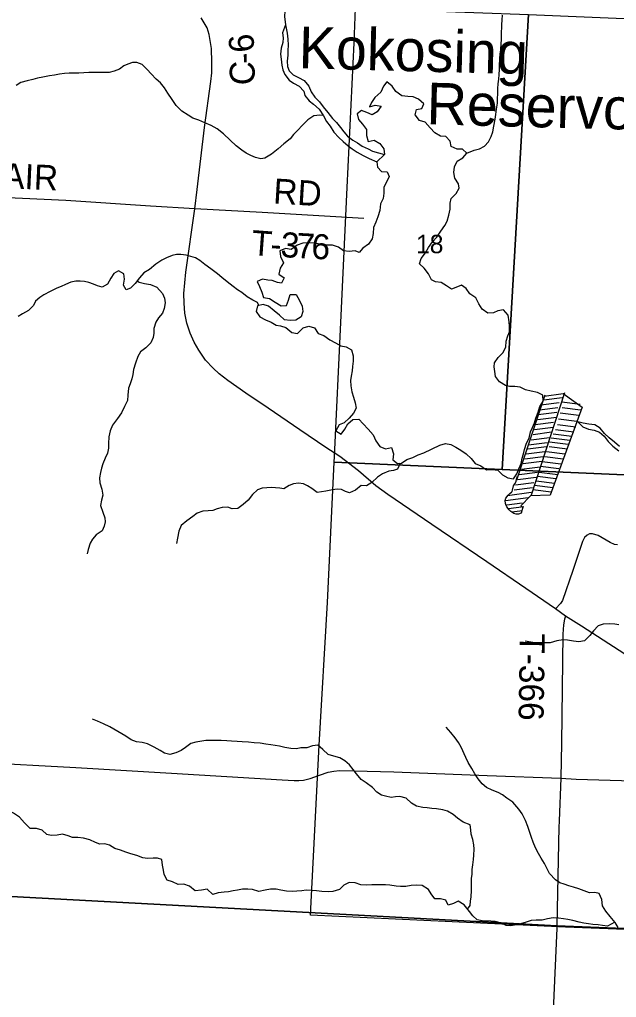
# Model space of a CAD drawing. Extents: x 1759416 to 2214760, y 252598 to 1116833.
# Drawn here: x 1940879 to 1948045, y 906081 to 917809 of the extents above; entities that cross this region are included whole.
import ezdxf

# ---------------------------------------------------------------- set-up
doc = ezdxf.new("R2010")
doc.units = 0
for name, color, linetype in [('GM_X_County_Road', 7, 'Continuous'), ('GM_X_County_Road_Text', 7, 'Continuous'), ('GM_X_Major_Lake', 7, 'Continuous'), ('GM_X_Major_Lake_Text', 7, 'Continuous'), ('GM_X_Major_River', 7, 'Continuous'), ('GM_X_Minor_Lake', 7, 'Continuous'), ('GM_X_Minor_River', 7, 'Continuous'), ('GM_X_Section', 7, 'Continuous'), ('GM_X_Section_Text', 7, 'Continuous'), ('GM_X_Township', 7, 'Continuous'), ('GM_X_Township_Road', 7, 'Continuous'), ('GM_X_Township_Road_Text', 7, 'Continuous')]:
    doc.layers.add(name, color=color, linetype=linetype)

msp = doc.modelspace()

# ---------------------------------------------------------------- linework, layer by layer
at = {"layer": 'GM_X_County_Road'}
for points in [[(1948338, 910072), (1947626, 910533), (1947434, 910655), (1947314, 910743), (1946955, 910986), (1946490, 911306), (1945827, 911752), (1945302, 912113), (1945158, 912217), (1944947, 912395), (1944725, 912567), (1944554, 912676), (1944244, 912890), (1943863, 913147), (1943594, 913328), (1943380, 913478), (1943274, 913560), (1943203, 913628), (1943113, 913722), (1943031, 913842), (1942974, 913940), (1942926, 914046), (1942888, 914168), (1942865, 914288), (1942855, 914406), (1942853, 914523), (1942876, 914779), (1942984, 915539), (1943011, 915772), (1943099, 916512), (1943174, 917067), (1943186, 917169), (1943187, 917298), (1943183, 917462), (1943156, 917630), (1943130, 917708), (1943058, 917828)], [(1940369, 908903), (1941554, 908838), (1942702, 908771), (1944033, 908690), (1944174, 908682), (1944232, 908682), (1944288, 908687), (1944368, 908708), (1944479, 908747), (1944583, 908783), (1944653, 908795), (1944719, 908802), (1944891, 908798), (1945374, 908788), (1946494, 908742), (1947376, 908712), (1947560, 908700), (1948378, 908674)]]:
    msp.add_lwpolyline(points, dxfattribs=at)
at = {"layer": 'GM_X_Major_Lake'}
for points in [[(1946954, 913368), (1946890, 913398), (1946826, 913408), (1946761, 913406), (1946711, 913418), (1946641, 913463), (1946593, 913527), (1946584, 913589), (1946578, 913643), (1946582, 913693), (1946624, 913756), (1946680, 913812), (1946715, 913880), (1946721, 913952), (1946739, 914014), (1946759, 914064), (1946761, 914132), (1946758, 914184), (1946744, 914263), (1946688, 914327), (1946622, 914317), (1946570, 914293), (1946501, 914289), (1946433, 914334), (1946392, 914400), (1946356, 914470), (1946286, 914518), (1946242, 914583), (1946184, 914623), (1946118, 914597), (1946065, 914575), (1946005, 914615), (1945941, 914656), (1945873, 914662), (1945823, 914686), (1945790, 914760), (1945738, 914826), (1945682, 914877), (1945700, 914943), (1945754, 915009), (1945790, 915075), (1945837, 915141), (1945887, 915199), (1945937, 915271), (1945983, 915337), (1946012, 915391), (1946034, 915462), (1946050, 915534), (1946050, 915606), (1946060, 915662), (1946121, 915722), (1946155, 915786), (1946147, 915840), (1946103, 915905), (1946091, 915973), (1946100, 916041), (1946134, 916111), (1946200, 916151), (1946250, 916205), (1946198, 916255), (1946132, 916255), (1946062, 916286), (1946048, 916350), (1945998, 916406), (1945934, 916412), (1945866, 916451), (1945808, 916511), (1945748, 916577), (1945680, 916597), (1945628, 916664), (1945643, 916730), (1945709, 916740), (1945731, 916798), (1945669, 916854), (1945605, 916882), (1945539, 916885), (1945469, 916893), (1945397, 916945), (1945353, 917011), (1945289, 917062), (1945247, 917010), (1945217, 916939), (1945146, 916875), (1945106, 916813), (1945082, 916761), (1945150, 916781), (1945222, 916771), (1945174, 916701), (1945112, 916667), (1945048, 916693), (1944984, 916717), (1944931, 916679), (1944949, 916611), (1944997, 916553), (1945043, 916491), (1945043, 916418), (1945063, 916346), (1945135, 916364), (1945203, 916322), (1945253, 916258), (1945259, 916191)], [(1945259, 916191), (1945170, 916103)], [(1945170, 916103), (1945178, 916037), (1945224, 915985), (1945292, 915981), (1945318, 915926), (1945253, 915794), (1945251, 915728), (1945245, 915664), (1945213, 915598), (1945205, 915520), (1945182, 915441), (1945158, 915377), (1945130, 915313), (1945126, 915243), (1945112, 915177), (1945067, 915115), (1945001, 915065), (1944957, 915013), (1944907, 915035), (1944837, 915025), (1944769, 915033), (1944709, 915080), (1944634, 915102), (1944570, 915104), (1944514, 915114), (1944462, 915120), (1944412, 915126), (1944344, 915131), (1944278, 915127), (1944212, 915103), (1944141, 915051), (1944071, 915063), (1944003, 915035), (1944011, 914967), (1944047, 914889), (1944007, 914827), (1943990, 914756), (1944054, 914710), (1944024, 914646), (1943974, 914656), (1943910, 914678), (1943858, 914685), (1943794, 914697), (1943732, 914669), (1943760, 914607), (1943789, 914538), (1943809, 914474), (1943881, 914464), (1943949, 914418), (1944021, 914375), (1944082, 914379), (1944106, 914443), (1944128, 914513), (1944198, 914513), (1944240, 914441), (1944272, 914373), (1944278, 914309), (1944261, 914244), (1944197, 914202), (1944129, 914199), (1944061, 914209), (1943999, 914263), (1943935, 914315), (1943869, 914370), (1943803, 914392), (1943735, 914376), (1943719, 914308), (1943763, 914242), (1943833, 914207), (1943899, 914181), (1943961, 914143), (1944011, 914135), (1944077, 914117), (1944149, 914054), (1944217, 914044), (1944283, 914110), (1944351, 914132), (1944421, 914110), (1944465, 914043), (1944533, 914021), (1944603, 913967), (1944671, 913931), (1944735, 913896), (1944799, 913882), (1944863, 913848), (1944883, 913776), (1944885, 913712), (1944875, 913647), (1944871, 913595), (1944861, 913531), (1944854, 913479), (1944856, 913415), (1944868, 913343), (1944888, 913278), (1944910, 913212), (1944920, 913148), (1944887, 913086), (1944837, 913026), (1944777, 912972), (1944715, 912948), (1944674, 912876)], [(1945926, 912704), (1945992, 912726), (1946056, 912714), (1946116, 912680), (1946178, 912644), (1946242, 912599), (1946300, 912545), (1946350, 912485), (1946418, 912455), (1946486, 912410), (1946554, 912414), (1946620, 912406), (1946678, 912348), (1946740, 912311), (1946808, 912301), (1946847, 912359), (1946873, 912419), (1946899, 912483), (1946911, 912550), (1946927, 912602), (1946942, 912654), (1946966, 912728), (1946998, 912790), (1947014, 912864), (1947037, 912918), (1947059, 912970), (1947077, 913026), (1947103, 913101), (1947125, 913167), (1947164, 913233), (1947162, 913305), (1947096, 913335), (1947022, 913350), (1946954, 913368)], [(1944674, 912876), (1944738, 912836), (1944785, 912898), (1944819, 912962), (1944879, 913012), (1944951, 913017), (1945005, 912959), (1945065, 912895), (1945123, 912827), (1945157, 912758), (1945205, 912688), (1945273, 912660), (1945345, 912676), (1945369, 912601), (1945361, 912529), (1945415, 912483), (1945465, 912489), (1945527, 912533), (1945599, 912557), (1945665, 912587), (1945733, 912611), (1945926, 912704)]]:
    msp.add_lwpolyline(points, dxfattribs=at)
at = {"layer": 'GM_X_Major_River'}
for points in [[(1945259, 916191), (1945170, 916103)], [(1947580, 912983), (1947642, 912923), (1947708, 912897), (1947776, 912884), (1947842, 912862), (1947898, 912812), (1947944, 912750), (1948000, 912693), (1948072, 912637)], [(1948080, 912689), (1948020, 912742), (1947956, 912792), (1947902, 912846), (1947848, 912910), (1947784, 912947), (1947712, 912957), (1947646, 912969), (1947580, 912983)]]:
    msp.add_lwpolyline(points, dxfattribs=at)
at = {"layer": 'GM_X_Minor_Lake'}
for points in [[(1945259, 916191), (1945170, 916103)], [(1947175, 913293), (1947404, 913325), (1947635, 913158), (1947249, 912104), (1947012, 912098), (1946895, 911976), (1946921, 911960), (1946902, 911890), (1946868, 911878), (1946840, 911876), (1946812, 911883), (1946778, 911907), (1946758, 911927), (1946730, 911964), (1946718, 911992), (1946714, 912006), (1946707, 912042), (1946717, 912070), (1946745, 912106), (1946767, 912130), (1946784, 912142), (1946794, 912148), (1946798, 912164), (1946810, 912216), (1946823, 912240), (1946839, 912268), (1946843, 912296), (1946856, 912334)], [(1947185, 913304), (1946845, 912286)], [(1947422, 913331), (1947022, 912104), (1947013, 912097)], [(1947393, 913273), (1947172, 913244)], [(1947341, 913153), (1947120, 913125)], [(1947358, 913213), (1947137, 913185)], [(1947387, 913223), (1947608, 913195)], [(1947393, 913156), (1947614, 913127)], [(1947323, 913034), (1947102, 913006)], [(1947327, 913094), (1947106, 913066)], [(1947348, 913021), (1947569, 912992)], [(1947370, 913091), (1947591, 913063)], [(1947283, 912918), (1947062, 912890)], [(1947288, 912975), (1947067, 912947)], [(1947336, 912953), (1947557, 912925)], [(1947240, 912793), (1947019, 912765)], [(1947266, 912859), (1947045, 912830)], [(1947262, 912794), (1947483, 912766)], [(1947286, 912840), (1947507, 912812)], [(1947311, 912893), (1947532, 912865)], [(1947203, 912683), (1946982, 912655)], [(1947211, 912734), (1946990, 912705)], [(1947235, 912690), (1947456, 912662)], [(1947242, 912746), (1947463, 912718)], [(1947166, 912564), (1946945, 912536)], [(1947183, 912626), (1946962, 912598)], [(1947184, 912568), (1947405, 912540)], [(1947203, 912630), (1947424, 912602)], [(1947127, 912442), (1946906, 912413)], [(1947147, 912507), (1946925, 912479)], [(1947132, 912451), (1947353, 912423)], [(1947154, 912510), (1947375, 912482)], [(1947081, 912317), (1946860, 912288)], [(1947098, 912376), (1946877, 912348)], [(1947096, 912332), (1947317, 912303)], [(1947118, 912382), (1947339, 912354)], [(1947052, 912254), (1946831, 912226)], [(1947060, 912225), (1947281, 912196)], [(1947080, 912278), (1947301, 912250)], [(1947021, 912135), (1946735, 912098)], [(1947038, 912191), (1946817, 912163)], [(1947041, 912171), (1947262, 912143)], [(1946983, 912072), (1946714, 912038)], [(1946912, 912007), (1946729, 911983)], [(1946933, 911964), (1946750, 911941)], [(1946916, 911918), (1946789, 911902)]]:
    msp.add_lwpolyline(points, dxfattribs=at)
at = {"layer": 'GM_X_Minor_River'}
for points in [[(1943706, 918546), (1943784, 918468), (1943834, 918402), (1943874, 918344), (1943918, 918278), (1943956, 918223), (1944006, 918151), (1944036, 918099), (1944054, 918045), (1944066, 917965), (1944064, 917911), (1944058, 917844), (1944073, 917745)], [(1946250, 916205), (1946338, 916241), (1946402, 916259), (1946460, 916292), (1946510, 916344), (1946542, 916408), (1946559, 916462), (1946573, 916530), (1946589, 916612), (1946597, 916671), (1946605, 916735), (1946615, 916805), (1946615, 916861), (1946619, 916919), (1946621, 916981), (1946625, 917038), (1946631, 917094), (1946635, 917150), (1946639, 917208), (1946641, 917270), (1946645, 917326), (1946651, 917397), (1946657, 917453), (1946661, 917515), (1946663, 917575), (1946665, 917625), (1946669, 917746), (1946673, 917806), (1946675, 917860)], [(1944073, 917745), (1944034, 917650), (1944044, 917588), (1944038, 917533), (1944020, 917467), (1944013, 917395), (1944019, 917333), (1944029, 917261), (1944041, 917205), (1944063, 917150), (1944115, 917082), (1944166, 917044), (1944234, 917008), (1944290, 916948), (1944304, 916898), (1944356, 916835), (1944406, 916795), (1944474, 916733), (1944526, 916653), (1944564, 916585), (1944606, 916529), (1944650, 916460), (1944710, 916396), (1944766, 916346), (1944824, 916294), (1944874, 916260), (1944934, 916218), (1945006, 916178), (1945078, 916143), (1945170, 916103)], [(1944073, 917745), (1944090, 917644), (1944100, 917574), (1944102, 917501), (1944100, 917437), (1944098, 917381), (1944090, 917311), (1944094, 917245), (1944114, 917195), (1944162, 917144), (1944226, 917114), (1944294, 917076), (1944352, 917010), (1944378, 916942), (1944424, 916876), (1944478, 916823), (1944522, 916763), (1944578, 916693), (1944636, 916623), (1944684, 916573), (1944732, 916515), (1944774, 916462), (1944818, 916410), (1944882, 916362), (1944936, 916330), (1944992, 916292), (1945064, 916258), (1945118, 916232), (1945259, 916191)], [(1944523, 916657), (1944482, 916661), (1944410, 916655), (1944340, 916607), (1944271, 916539), (1944219, 916481), (1944169, 916430), (1944127, 916380), (1944053, 916318), (1943985, 916258), (1943905, 916196), (1943825, 916146), (1943774, 916140), (1943710, 916156), (1943654, 916180), (1943600, 916206), (1943546, 916242), (1943480, 916296), (1943406, 916364), (1943326, 916439), (1943252, 916497), (1943180, 916539), (1943104, 916571), (1943030, 916601), (1942960, 916627), (1942902, 916663), (1942829, 916711), (1942759, 916778), (1942711, 916848), (1942659, 916924), (1942621, 916988), (1942571, 917050), (1942521, 917093), (1942459, 917157), (1942411, 917209), (1942351, 917271), (1942289, 917295), (1942237, 917293), (1942181, 917273), (1942131, 917255), (1942081, 917215), (1942017, 917189), (1941956, 917175), (1941900, 917173), (1941822, 917173), (1941762, 917173), (1941710, 917173), (1941652, 917171), (1941590, 917167), (1941532, 917167), (1941474, 917165), (1941420, 917161), (1941360, 917153), (1941298, 917143), (1941237, 917135), (1941157, 917119), (1941095, 917105), (1941039, 917091), (1940969, 917075), (1940895, 917053), (1940839, 917019)], [(1943753, 914380), (1943735, 914415), (1943681, 914445), (1943611, 914483), (1943547, 914535), (1943495, 914567), (1943445, 914606), (1943373, 914662), (1943307, 914714), (1943255, 914758), (1943175, 914818), (1943105, 914872), (1943045, 914918), (1942993, 914949), (1942935, 914967), (1942881, 914981), (1942815, 914991), (1942764, 914989), (1942710, 914977), (1942642, 914951), (1942586, 914923), (1942514, 914876), (1942440, 914812), (1942370, 914770), (1942318, 914712), (1942268, 914644), (1942211, 914588), (1942161, 914568), (1942127, 914622), (1942139, 914694), (1942133, 914758), (1942069, 914796), (1942011, 914762), (1941977, 914708), (1941935, 914636), (1941869, 914598), (1941815, 914616), (1941765, 914634), (1941709, 914654), (1941659, 914668), (1941607, 914672), (1941555, 914670), (1941496, 914658), (1941430, 914630), (1941380, 914608), (1941328, 914588), (1941248, 914548), (1941172, 914506), (1941122, 914476), (1941072, 914432), (1941046, 914381), (1940986, 914319), (1940915, 914279), (1940861, 914249)], [(1942291, 914675), (1942316, 914658), (1942378, 914644), (1942450, 914630), (1942528, 914600), (1942594, 914525), (1942620, 914467), (1942628, 914411), (1942614, 914343), (1942594, 914287), (1942546, 914231), (1942514, 914179), (1942492, 914102), (1942490, 914046), (1942482, 913994), (1942455, 913930), (1942397, 913870), (1942331, 913822), (1942299, 913769), (1942271, 913689), (1942249, 913613), (1942241, 913551), (1942229, 913499), (1942209, 913441), (1942189, 913388), (1942181, 913302), (1942175, 913238), (1942139, 913166), (1942104, 913090), (1942056, 913023), (1941996, 912943), (1941968, 912875), (1941950, 912805), (1941946, 912723), (1941946, 912668), (1941936, 912608), (1941908, 912550), (1941880, 912482), (1941864, 912428), (1941850, 912376), (1941840, 912314), (1941842, 912251), (1941866, 912177), (1941878, 912103), (1941864, 912045), (1941852, 911979), (1941880, 911902), (1941904, 911834), (1941908, 911784), (1941897, 911734), (1941871, 911678), (1941799, 911630), (1941755, 911578), (1941725, 911527), (1941701, 911453), (1941691, 911399)], [(1945448, 912487), (1945417, 912415), (1945367, 912401), (1945311, 912391), (1945236, 912359), (1945178, 912319), (1945108, 912255), (1945044, 912217), (1944980, 912219), (1944914, 912166), (1944842, 912134), (1944792, 912148), (1944742, 912171), (1944690, 912177), (1944634, 912169), (1944557, 912153), (1944453, 912136), (1944387, 912183), (1944337, 912215), (1944287, 912239), (1944227, 912247), (1944169, 912239), (1944117, 912219), (1944053, 912179), (1944003, 912187), (1943953, 912193), (1943903, 912197), (1943848, 912193), (1943790, 912187), (1943736, 912167), (1943676, 912111), (1943622, 912046), (1943564, 911994), (1943500, 911946), (1943430, 911942), (1943380, 911960), (1943310, 911958), (1943253, 911940), (1943199, 911920), (1943145, 911916), (1943081, 911914), (1943011, 911890), (1942959, 911850), (1942887, 911796), (1942821, 911740), (1942793, 911672), (1942777, 911587), (1942763, 911523)], [(1948075, 910548), (1948025, 910558), (1947958, 910561), (1947884, 910558), (1947826, 910536), (1947771, 910479), (1947725, 910420), (1947660, 910357), (1947594, 910345), (1947528, 910354), (1947455, 910367), (1947403, 910371), (1947327, 910356), (1947249, 910335), (1947193, 910332), (1947139, 910334), (1947067, 910335), (1947015, 910342), (1946948, 910353)], [(1946258, 907140), (1946290, 907185), (1946292, 907235), (1946301, 907286), (1946305, 907362), (1946304, 907428), (1946305, 907508), (1946311, 907561), (1946314, 907615), (1946322, 907673), (1946329, 907735), (1946333, 907785), (1946336, 907860), (1946331, 907912), (1946319, 907974), (1946302, 908038), (1946297, 908092), (1946287, 908152), (1946206, 908183), (1946136, 908231), (1946083, 908276), (1946015, 908313), (1945960, 908329), (1945884, 908342), (1945830, 908345), (1945772, 908353), (1945720, 908360), (1945643, 908373), (1945583, 908411), (1945520, 908472), (1945444, 908490), (1945394, 908485), (1945342, 908478), (1945273, 908496), (1945223, 908507), (1945169, 908543), (1945116, 908598), (1945041, 908654), (1944979, 908693), (1944926, 908761), (1944883, 908814), (1944839, 908870), (1944784, 908917), (1944724, 908953), (1944653, 908974), (1944585, 908993), (1944520, 909053), (1944458, 909108), (1944394, 909100), (1944328, 909075), (1944256, 909074), (1944204, 909061), (1944135, 909065), (1944065, 909078), (1943999, 909093), (1943949, 909101), (1943897, 909110), (1943836, 909120), (1943768, 909129), (1943696, 909136), (1943628, 909143), (1943553, 909148), (1943493, 909152), (1943423, 909155), (1943367, 909158), (1943299, 909162), (1943233, 909163), (1943114, 909162), (1943044, 909151), (1942994, 909142), (1942936, 909126), (1942871, 909077), (1942819, 909044), (1942755, 909013), (1942685, 908996), (1942619, 909010), (1942566, 909041), (1942496, 909081), (1942417, 909124), (1942351, 909137), (1942283, 909148), (1942220, 909172), (1942154, 909213), (1941962, 909325), (1941886, 909363), (1941813, 909396), (1941753, 909419)], [(1948064, 906920), (1948028, 906978), (1947971, 907052), (1947918, 907117), (1947878, 907181), (1947869, 907257), (1947838, 907329), (1947784, 907338), (1947720, 907334), (1947659, 907359), (1947593, 907384), (1947527, 907402), (1947472, 907419), (1947416, 907439), (1947366, 907456), (1947311, 907490), (1947240, 907569), (1947179, 907689), (1947142, 907750), (1947110, 907808), (1947073, 907876), (1947044, 907942), (1947024, 908000), (1946982, 908132), (1946954, 908204), (1946913, 908281), (1946874, 908339), (1946799, 908422), (1946727, 908472), (1946676, 908509), (1946624, 908539), (1946551, 908568), (1946483, 908597), (1946432, 908641), (1946384, 908701), (1946345, 908762), (1946310, 908826), (1946265, 908900), (1946237, 908958), (1946179, 909083), (1946149, 909139), (1946108, 909195), (1946055, 909258), (1945999, 909324)], [(1941902, 907923), (1941844, 907920), (1941792, 907940), (1941721, 907971), (1941647, 907992), (1941579, 907997), (1941515, 907999), (1941464, 908020), (1941396, 908037), (1941330, 908025), (1941260, 908022), (1941206, 908033), (1941149, 908087), (1941081, 908108), (1941005, 908107), (1940940, 908173), (1940879, 908244), (1940808, 908292), (1940750, 908323), (1940700, 908335), (1940647, 908342), (1940593, 908357)], [(1948024, 906983), (1947936, 906937), (1947878, 906944), (1947826, 906952), (1947762, 906957), (1947709, 906964), (1947655, 906972), (1947595, 906985), (1947519, 907002), (1947460, 907016), (1947410, 907023), (1947350, 907033), (1947284, 907036), (1947218, 907025), (1947154, 907006), (1947082, 907006), (1947020, 907003), (1946960, 906984), (1946894, 906965), (1946842, 906951), (1946776, 906938), (1946720, 906945), (1946663, 906971), (1946589, 906990), (1946535, 906996), (1946434, 906998), (1946374, 907012), (1946320, 907059), (1946281, 907111), (1946218, 907191), (1946146, 907236), (1946088, 907209), (1946026, 907186), (1945995, 907246), (1945931, 907264), (1945865, 907265), (1945820, 907324), (1945787, 907376), (1945711, 907422), (1945639, 907427), (1945581, 907422), (1945517, 907413), (1945452, 907411), (1945402, 907414), (1945324, 907427), (1945274, 907433), (1945166, 907432), (1945110, 907433), (1945041, 907426), (1944975, 907433), (1944907, 907455), (1944835, 907460), (1944773, 907427), (1944719, 907374), (1944641, 907350), (1944589, 907347), (1944507, 907350), (1944443, 907359), (1944391, 907365), (1944319, 907366), (1944269, 907361), (1944208, 907355), (1944152, 907352), (1944084, 907355), (1944014, 907369), (1943960, 907378), (1943892, 907381), (1943826, 907369), (1943750, 907352), (1943677, 907375), (1943621, 907378), (1943555, 907380), (1943495, 907367), (1943443, 907358), (1943389, 907348), (1943335, 907345), (1943265, 907334), (1943201, 907315), (1943130, 907379), (1943062, 907368), (1942988, 907361), (1942921, 907417), (1942851, 907440), (1942783, 907437), (1942714, 907468), (1942650, 907486), (1942617, 907556), (1942609, 907606), (1942594, 907668), (1942587, 907734), (1942537, 907751), (1942483, 907751), (1942417, 907748), (1942359, 907755), (1942288, 907781), (1942216, 907804), (1942156, 907821), (1942093, 907845), (1942023, 907866), (1941960, 907905), (1941902, 907923)]]:
    msp.add_lwpolyline(points, dxfattribs=at)
at = {"layer": 'GM_X_Section'}
for points in [[(1946987, 917871), (1946673, 912411), (1944656, 912501), (1944659, 912568), (1944737, 914175), (1944812, 915795), (1944895, 917531), (1944914, 917946)], [(1952344, 917647), (1952087, 912177), (1946673, 912411), (1946987, 917871)], [(1946673, 912411), (1952087, 912177), (1951854, 906759), (1950294, 906813), (1947431, 906922), (1944372, 907066), (1944475, 909105), (1944574, 910818), (1944656, 912501)]]:
    msp.add_lwpolyline(points, close=True, dxfattribs=at)
at = {"layer": 'GM_X_Township'}
for points in [[(1957760, 921682), (1957585, 915650), (1957347, 909188), (1957243, 906546), (1956080, 906593), (1955889, 906604), (1953807, 906686), (1952212, 906748), (1952068, 906753), (1947328, 906938), (1937425, 907470), (1932937, 907680), (1930733, 907844), (1930824, 909461), (1930891, 910644), (1931168, 914595), (1931473, 919044)], [(1937425, 907470), (1947328, 906938), (1952068, 906753), (1952212, 906748), (1953807, 906686), (1955889, 906604), (1956080, 906593), (1957243, 906546), (1957178, 904952)]]:
    msp.add_lwpolyline(points, dxfattribs=at)
at = {"layer": 'GM_X_Township_Road'}
for points in [[(1945011, 915422), (1944539, 915452), (1943790, 915494), (1942984, 915539), (1942450, 915572), (1941433, 915638), (1940303, 915689)], [(1948058, 911507), (1948022, 911511), (1947968, 911535), (1947824, 911621), (1947758, 911642), (1947722, 911640), (1947692, 911626), (1947662, 911596), (1947638, 911550), (1947519, 911201), (1947396, 910842), (1947372, 910805), (1947314, 910743)], [(1947434, 910655), (1947420, 910617), (1947407, 910549), (1947401, 910438), (1947386, 909130), (1947376, 908712), (1947357, 908198)], [(1947357, 908198), (1947356, 908189), (1947354, 908126), (1947328, 906938), (1947327, 906913)], [(1947327, 906913), (1947247, 905115)]]:
    msp.add_lwpolyline(points, dxfattribs=at)

# ---------------------------------------------------------------- texts
at = {"layer": 'GM_X_County_Road_Text'}
for s, rotation, p in [('6', 95.1059, (1943702, 917426)), ('-', 91.0978, (1943706, 917280)), ('C', 88.0794, (1943697, 917016))]:
    msp.add_text(s, height=300, rotation=rotation, dxfattribs=at).set_placement(p)
at = {"layer": 'GM_X_Major_Lake_Text'}
for s, rotation, p in [('Kokosing', 358.4732, (1944225, 917225)), ('Reservoir', 358.4735, (1945761, 916553))]:
    msp.add_text(s, height=500, rotation=rotation, dxfattribs=at).set_placement(p)
at = {"layer": 'GM_X_Section_Text'}
msp.add_text('18', height=221, rotation=0, dxfattribs=at).set_placement((1945639, 915006))
at = {"layer": 'GM_X_Township_Road_Text'}
for s, rotation, p in [('BLAIR', 357.493, (1940177, 915810)), ('RD', 356.5467, (1943919, 915604)), ('T', 355.7962, (1943655, 914985)), ('3', 356.8457, (1944008, 914961)), ('7', 356.9087, (1944193, 914951)), ('6', 356.9242, (1944377, 914941)), ('-', 356.6884, (1943884, 914968)), ('T-366', 269.1579, (1946885, 910450))]:
    msp.add_text(s, height=300, rotation=rotation, dxfattribs=at).set_placement(p)

doc.saveas('drawing.dxf')
